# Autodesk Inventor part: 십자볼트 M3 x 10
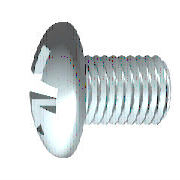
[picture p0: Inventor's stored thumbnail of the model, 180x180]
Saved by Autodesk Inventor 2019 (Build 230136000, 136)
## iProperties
IsCustomPart: 0
Created: 2012-02
Part Number: 십자볼트 M3 x 10
Material: 스테인리스강
Description: 십자 오목 머리 나사
Document SubType Name: Modeling
Standard: KS B 1023
Designer: mduedu
Standards Organization: KS
Language: ko-KR
Size Designation: A  M 3 x 10 - H
Categories: <MemberInstance><Categories><Category DisplayName="조임쇠" InternalName="e4da775c-781d-43d5-af7c-5136215cf5a6" Mnemonic="FSTN"><Category DisplayName="볼트" InternalN
Density: 1 g/cm^3
Appearance: 반광택
Author: mduedu
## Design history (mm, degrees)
body "Solid1"
workplane "Work Plane3"
sketch "스케치2"
  geometry: L1 (-3.72, 0)-(3.72, 0) reference; L2 (0, -3.72)-(0, 3.72) reference; L3 (0, 1.5)-(0, 0); L4 (0, 0)-(1.5, 0); L5 (0, 0)-(1.879, 1.879); L6 (0.253, 1.479)-(0.261, 0.456); L7 (1.479, 0.253)-(0.456, 0.261); L8 (0.253, -1.479)-(0.261, -0.456); L9 (1.479, -0.253)-(0.456, -0.261); L10 (-0.253, 1.479)-(-0.261, 0.456); L11 (-1.479, 0.253)-(-0.456, 0.261); L12 (-1.479, -0.253)-(-0.456, -0.261); L13 (-0.253, -1.479)-(-0.261, -0.456); A1 r 0.45 centre (0, 0) between (0.45, 0) and (0, 0.45); A2 r 1.5 centre (0, 0) between (1.5, 0) and (1.479, 0.253); A3 r 1.5 centre (0, 0) between (0.253, 1.479) and (0, 1.5); A4 r 1.5 centre (0, 0) between (1.479, 0.253) and (0.253, 1.479); A5 r 1.5 centre (0, 0) between (0, -1.5) and (0.253, -1.479); A6 r 1.5 centre (0, 0) between (0.253, -1.479) and (1.479, -0.253); A7 r 1.5 centre (0, 0) between (1.479, -0.253) and (1.5, 0); A8 r 1.5 centre (0, 0) between (-1.479, 0.253) and (-1.5, 0); A9 r 1.5 centre (0, 0) between (-0.253, 1.479) and (-1.479, 0.253); A10 r 1.5 centre (0, 0) between (0, 1.5) and (-0.253, 1.479); A11 r 1.5 centre (0, 0) between (-1.5, 0) and (-1.479, -0.253); A12 r 1.5 centre (0, 0) between (-1.479, -0.253) and (-0.253, -1.479); A13 r 1.5 centre (0, 0) between (-0.253, -1.479) and (0, -1.5); A14 r 0.525 centre (0, 0) between (0.525, 0) and (0, 0.525); A15 r 0.197 centre (0.457, 0.457) between (0.261, 0.456) and (0.456, 0.261); A16 r 0.197 centre (0.457, -0.457) between (0.456, -0.261) and (0.261, -0.456); A17 r 0.197 centre (-0.457, 0.457) between (-0.456, 0.261) and (-0.261, 0.456); A18 r 0.197 centre (-0.457, -0.457) between (-0.261, -0.456) and (-0.456, -0.261); 1 further point
  constraints: 38 point on circle, 22 end point, 19 symmetric about line, 18 centre point, 4 coincident, 3 collinear, 3 point on line, 3 tangent, 1 perpendicular, 21 other
  dimensions: "d4" = 45 deg angle of L5 L4; "d5" = 0.9 diameter of A1 (= 0.3 x SDM); "d6" = 3 diameter of A4 (= SDM); "d7" = 0.2525 distance from line of L6.start L3 (= 0.5 x SBR); "d14" = 1.05 diameter of A14 (= 0.35 x SDM)
extrude "슬롯" join sketch "스케치2" taper "d15" = 5 deg; stored distance "d54" = 10
revolve "절단부" stored, may be unused: angle "d56" = 90 deg
revolve "본체" stored, may be unused: angle "d18" = 90 deg
workplane "Work Plane1"
sketch "스케치1"
  geometry: L1 (10, 0)-(10, 1.5); L2 (10, 1.5)-(1, 1.5); L3 (3.962, 5.08)-(3.962, 5.08); L4 (-2.4, 0)-(-2.4, 2.59); L5 (-2.2, 1.4)-(-1.036, 0.82); L6 (-1.036, 0.82)-(-0.6, 0); L7 (-0.6, 0)-(10, 0); L8 (-5.105, 0)-(12.517, 0) reference; L9 (0, -1.016)-(0, 6.096) reference; L10 (-2.2, 1.4)-(-2.4, 1.5); L11 (-1.636, 2.657)-(-2.4, 2.59); L12 (-1.636, 2.657)-(0, 2.8); L13 (0, 2.8)-(0, 1.347); L14 (0, 1.347)-(0.693, 1.347); L15 (0.693, 1.347)-(1, 1.5); L16 (1, 1.5)-(0, 1.5); A1 r 5 centre (2.6, 0) between (-1.636, 2.657) and (-2.4, 0)
  constraints: 28 end point, 5 point on line, 4 collinear, 4 point on circle, 3 parallel, 2 perpendicular, 1 centre point, 1 horizontal, 1 tangent
  dimensions: "d1" = 3 diameter of L2 L7 (= GD); "d2" = 1.8 distance from line of L6.end L4 (= STI); "d11" = 3 diameter of L10.end L7 (= SDM); "d12" = 62 deg angle of L6 L7; "d13" = 26.5 deg angle of L5 L7; "d17" = 5.6 diameter of L12.end L7 (= KOD); "d19" = 5 deg angle of L12 L7 (= KEWI); "d20" = 2.4 distance between parallel lines of L4 L13 (= KOH); "d21" = 5 radius of A1 (= KR); "d23" = 2.6935 diameter of L14 L7 (= BDM); "d24" = 9 distance of L1.end L2.end (= GEL); "d25" = 0.30673 horizontal distance of L14.end L2.end (= GAL); "d28" = 10 distance between parallel lines of L1 L13 (= NLG)
fillet "모깎기1" dims "d29" = 1.2 (= RR)
fillet "모깎기2" dims "d16" = 0.101 (= 0.2 x SBR)
feature "스레드" dims "d8" = 9 (= GEL), "d9" = 0
chamfer "모따기1" distance "d26" = 0.30673 (= -0.5 x SPD + 0.5 x GD); stored, may be unused: second distance "d27" = 0.30683 (computed from GUL), angle "d78" = 45 deg
other parameters: "GD" = 3 (= NND) [user parameter; used in 2 equation terms], "NLG" = 10 [user parameter; used in 1 equation term], "GEL" = 9 [user parameter; used in 2 equation terms], "KOD" = 5.6 [user parameter; used in 1 equation term], "KOH" = 2.4 [user parameter; used in 2 equation terms], "SDM" = 3 [user parameter; used in 4 equation terms], "STI" = 1.8 [user parameter; used in 1 equation term], "SBR" = 0.505 [user parameter; used in 2 equation terms], "GAL" = 0.30673 (= 0.61345 x PTC) [user parameter; used in 1 equation term], "SPD" = 2.38655 (= NND - 1.2269 x PTC) [user parameter; used in 1 equation term], "KEWI" = 5 deg [user parameter; used in 1 equation term], "d3" = -2.4 (= -KOH), "d10" = 0, "KR" = 5 [user parameter; used in 1 equation term], "BDM" = 2.6935 [user parameter; used in 1 equation term], "GUL" = 0.30673 (= 0.61345 x PTC) [user parameter; used in 1 equation term], "RR" = 1.2 [user parameter; used in 1 equation term], "d79" = 0, "d80" = 0, "PTC" = 0.5 [user parameter; used in 5 equation terms], "THREADDIA" = 3 [user parameter; used in 1 equation term], "TOA" = 30 deg [user parameter], "NND" = 3 [user parameter; used in 2 equation terms], "GD1" = 2.38655 (= THREADDIA - 1.2269 x PTC) [user parameter]
